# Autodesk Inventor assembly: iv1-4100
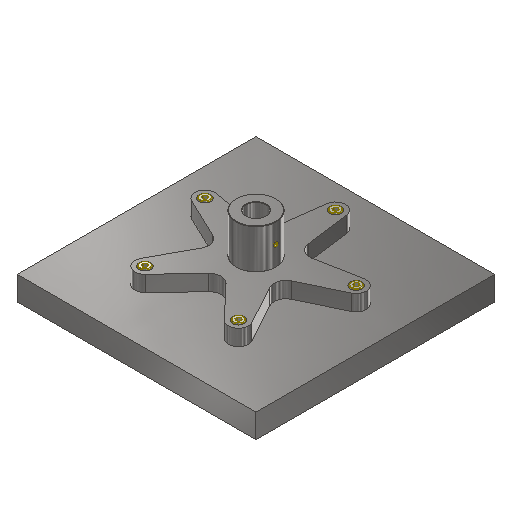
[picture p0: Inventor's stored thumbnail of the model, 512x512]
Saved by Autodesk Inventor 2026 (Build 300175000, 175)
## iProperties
Created: 2022-01
Part Number: iv1-4100
Document SubType Name: Assembly
Designer: Lars Bertram Pedersen
Mass: 24306.7 g
Surface Area: 2971.21 cm^2
Volume: 3096.4 cm^3
Density: 7.85 g/cm^3
Author: Lars Bertram Pedersen
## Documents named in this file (6)
- C:\INV GR\INV GR Part\iv1-4100.iam
- C:\INV GR\INV GR Part\iv1-3800.ipt
- C:\INV GR\INV GR Part\iv1-3700.ipt
- C:\INV GR\INV GR Part\iv1-3900.ipt
- C:\INV GR\INV GR Assembly\DIN 916 - M6  x  12.ipt
- C:\INV GR\INV GR Assembly\DIN 912 - M8 x 1,25 x 25 x 21,875.ipt
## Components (9 placed, 5 different names)
1. iv1-3800:1 — Mate:1, Mate:2, Mate:3, Angle:1
2. iv1-3700:1 — Mate:1, Mate:2, Mate:3, Mate:4, Mate:5
3. DIN 912 - M8 x 1,25 x 25 x 21,875:1
4. DIN 912 - M8 x 1,25 x 25 x 21,875:2
5. DIN 912 - M8 x 1,25 x 25 x 21,875:3
6. DIN 912 - M8 x 1,25 x 25 x 21,875:4
7. DIN 912 - M8 x 1,25 x 25 x 21,875:5
8. iv1-3900:1 — Mate:4, Mate:5, Angle:1
9. DIN 916 - M6  x  12:1
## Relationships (6: Mate 5, Angle 1)
- Mate:1: iv1-3800:1 ↔ iv1-3700:1
- Mate:2: iv1-3800:1 ↔ iv1-3700:1
- Mate:3: iv1-3800:1 ↔ iv1-3700:1
- Mate:4: iv1-3700:1 ↔ iv1-3900:1
- Mate:5: iv1-3700:1 ↔ iv1-3900:1
- Angle:1: iv1-3800:1 ↔ iv1-3900:1
